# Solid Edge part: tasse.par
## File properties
Author: Dieter
Template: Normal.par
Last saved by: Dieter
Revision: 1
Application: Solid Edge
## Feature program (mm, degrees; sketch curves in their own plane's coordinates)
sketch for "unnamed Protrusion 1" plane through (0, 0, 0) normal (0, 0, 1) x-axis (1, 0, 0)
  circle centre (0, 0) radius 30
extrude "unnamed Protrusion 1" add finite 80 along +normal
sketch for "unnamed RevolvedProtrusion 1" plane through (20, 0, 0) normal (1, 0, 0) x-axis (0, 1, 0)
  circle centre (0, 63.5158) radius 5
revolve "unnamed RevolvedProtrusion 1" add finite about sketch line (-12.6394, 36.2926) -> (14.5839, 36.2926)
sketch for "unnamed Cutout 1" plane through (0, 0, 80) normal (0, 0, 1) x-axis (1, 0, 0)
  circle centre (0, 0) radius 25
extrude "unnamed Cutout 1" cut finite 73 along -normal
fillet "unnamed Round 1"
